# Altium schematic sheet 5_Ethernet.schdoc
size 309 x 223 mm; Symbol: Artery_A4; Device: Artery_A4; Company: Artery Technology; Drawed: SD; Version: 1.3; Page Size: A4; @Project Name: AT-START-A403A V1.3; @Page Count: 5; @Update Date: 2023-11-22; @Create Date: 2022-12-01; @Schematic Name: AT_START_A403A; @Page No: 5; @Page Name: Ethernet
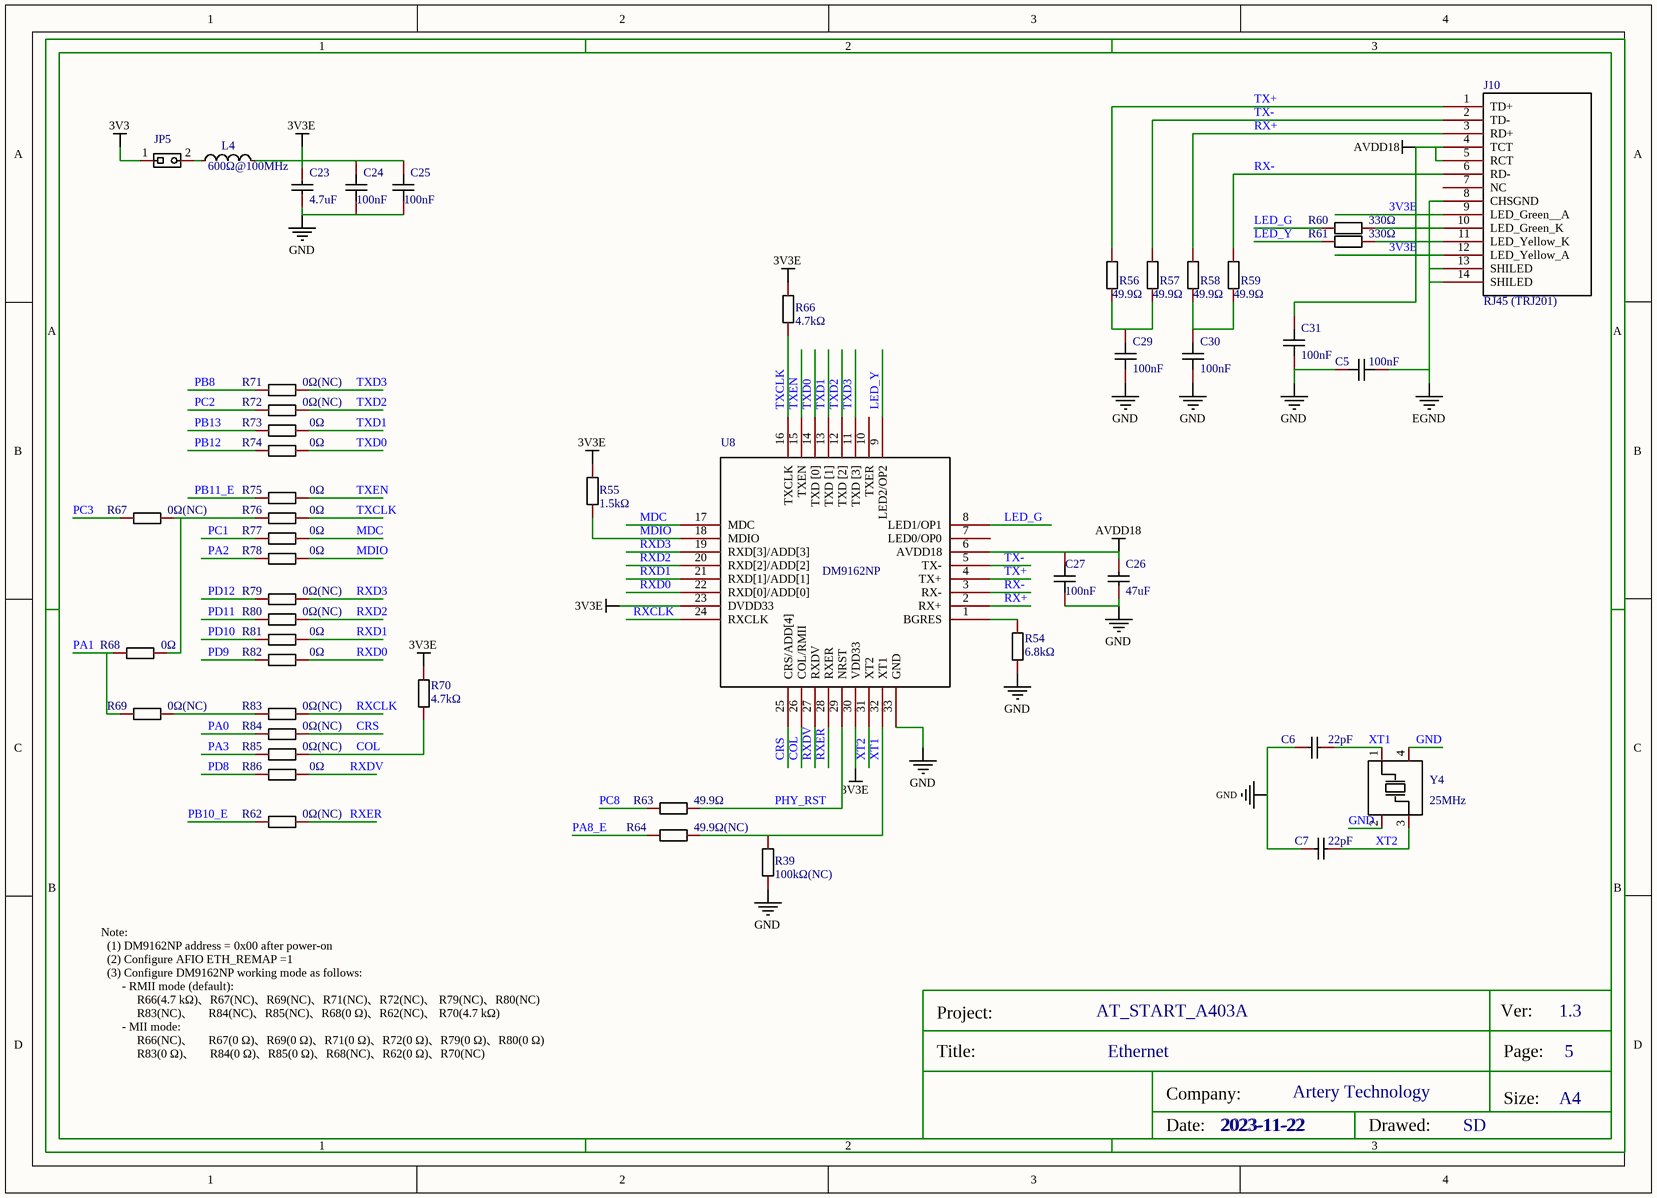
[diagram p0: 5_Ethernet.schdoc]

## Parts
C5  value 100nF  [C0603]  (hidden comment: CC0603KRX7R9BB104)
C6  22pF  [C0603]
C7  22pF  [C0603]
C23  value 4.7uF  [C0603]  (hidden comment: CL10A475KO8NNNC)
C24  value 100nF  [C0603]  (hidden comment: CC0603KRX7R9BB104)
C25  value 100nF  [C0603]  (hidden comment: CC0603KRX7R9BB104)
C26  value 47uF  [C0805]  (hidden comment: CL21A476MQYNNNE)
C27  value 100nF  [C0603]  (hidden comment: CC0603KRX7R9BB104)
C29  value 100nF  [C0603]  (hidden comment: CC0603KRX7R9BB104)
C30  value 100nF  [C0603]  (hidden comment: CC0603KRX7R9BB104)
C31  value 100nF  [C0603]  (hidden comment: CC0603KRX7R9BB104)
J10  RJ45 (TRJ201)  [HR911105A]
JP5  1X2P_2.54M  [HDR1X2]  (value not drawn)
L4  Impedance @ Frequency: 600Ω@100MHz  [L0805]  (hidden comment: GZ2012D601TF)
R39  value 100kΩ(NC)  [R0603]  (hidden comment: 0603WAF1003T5E)
R54  value 6.8kΩ  [R0603]  (hidden comment: 0603WAF6801T5E)
R55  value 1.5kΩ  [R0603]  (hidden comment: 0603WAF1501T5E)
R56  value 49.9Ω  [R0603]  (hidden comment: 0603WAF499JT5E)
R57  value 49.9Ω  [R0603]  (hidden comment: 0603WAF499JT5E)
R58  value 49.9Ω  [R0603]  (hidden comment: 0603WAF499JT5E)
R59  value 49.9Ω  [R0603]  (hidden comment: 0603WAF499JT5E)
R60  value 330Ω  [R0603]  (hidden comment: 0603WAF3300T5E)
R61  value 330Ω  [R0603]  (hidden comment: 0603WAF3300T5E)
R62  value 0Ω(NC)  [R0603]  (hidden comment: 0603WAF0000T5E)
R63  value 49.9Ω  [R0603]  (hidden comment: 0603WAF499JT5E)
R64  value 49.9Ω(NC)  [R0603]  (hidden comment: 0603WAF499JT5E)
R66  value 4.7kΩ  [R0603]  (hidden comment: 0603WAF4701T5E)
R67  value 0Ω(NC)  [R0603]  (hidden comment: 0603WAF0000T5E)
R68  value 0Ω  [R0603]  (hidden comment: 0603WAF0000T5E)
R69  value 0Ω(NC)  [R0603]  (hidden comment: 0603WAF0000T5E)
R70  value 4.7kΩ  [R0603]  (hidden comment: 0603WAF4701T5E)
R71  value 0Ω(NC)  [R0603]  (hidden comment: 0603WAF0000T5E)
R72  value 0Ω(NC)  [R0603]  (hidden comment: 0603WAF0000T5E)
R73  value 0Ω  [R0603]  (hidden comment: 0603WAF0000T5E)
R74  value 0Ω  [R0603]  (hidden comment: 0603WAF0000T5E)
R75  value 0Ω  [R0603]  (hidden comment: 0603WAF0000T5E)
R76  value 0Ω  [R0603]  (hidden comment: 0603WAF0000T5E)
R77  value 0Ω  [R0603]  (hidden comment: 0603WAF0000T5E)
R78  value 0Ω  [R0603]  (hidden comment: 0603WAF0000T5E)
R79  value 0Ω(NC)  [R0603]  (hidden comment: 0603WAF0000T5E)
R80  value 0Ω(NC)  [R0603]  (hidden comment: 0603WAF0000T5E)
R81  value 0Ω  [R0603]  (hidden comment: 0603WAF0000T5E)
R82  value 0Ω  [R0603]  (hidden comment: 0603WAF0000T5E)
R83  value 0Ω(NC)  [R0603]  (hidden comment: 0603WAF0000T5E)
R84  value 0Ω(NC)  [R0603]  (hidden comment: 0603WAF0000T5E)
R85  value 0Ω(NC)  [R0603]  (hidden comment: 0603WAF0000T5E)
R86  value 0Ω  [R0603]  (hidden comment: 0603WAF0000T5E)
U8  DM9162NP  [DM9162NP]
Y4  25MHz  [CRYSTAL-SMD_4P-L5.0-W3.2-BL]

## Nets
3V3: JP5.1
3V3E: C23.2 C24.2 C25.2 J10.9(LED_Green__A) J10.12(LED_Yellow_A) L4.2 R55.1 R66.1 R70.1 U8.23(DVDD33) U8.30(VDD33)
AVDD18: C26.2 C27.2 C31.2 J10.4(TCT) J10.5(RCT) U8.6(AVDD18)
EGND: C5.1 J10.8(CHSGND) J10.13(SHILED) J10.14(SHILED)
GND: C5.2 C6.2 C7.2 C23.1 C24.1 C25.1 C26.1 C27.1 C29.1 C30.1 C31.1 R39.2 R54.1 U8.33(GND) Y4.2(GND) Y4.4(GND)
COL: R70.2 R85.2 U8.26(COL/RMII)
CRS: R84.2 U8.25(CRS/ADD[4])
LED_G: R60.1 U8.8(LED1/OP1)
LED_Y: R61.1 U8.9(LED2/OP2)
MDC: R77.1 U8.17(MDC)
MDIO: R55.2 R78.1 U8.18(MDIO)
PA0: R84.1
PA1: R68.1 R69.2
PA2: R78.2
PA3: R85.1
PA8_E: R64.2
PB8: R71.2
PB10_E: R62.1
PB11_E: R75.2
PB12: R74.2
PB13: R73.2
PC1: R77.2
PC2: R72.2
PC3: R67.2
PC8: R63.2
PD8: R86.1
PD9: R82.1
PD10: R81.1
PD11: R80.2
PD12: R79.2
PHY_RST: R63.1 U8.29(NRST)
RX+: J10.3(RD+) R58.2 U8.2(RX+)
RX-: J10.6(RD-) R59.2 U8.3(RX-)
RXCLK: R83.2 U8.24(RXCLK)
RXD0: R82.2 U8.22(RXD[0]/ADD[0])
RXD1: R81.2 U8.21(RXD[1]/ADD[1])
RXD2: R80.1 U8.20(RXD[2]/ADD[2])
RXD3: R79.1 U8.19(RXD[3]/ADD[3])
RXDV: R86.2 U8.27(RXDV)
RXER: R62.2 U8.28(RXER)
TX+: J10.1(TD+) R56.2 U8.4(TX+)
TX-: J10.2(TD-) R57.2 U8.5(TX-)
TXCLK: R66.2 R76.1 U8.16(TXCLK)
TXD0: R74.1 U8.14(TXD_[0])
TXD1: R73.1 U8.13(TXD_[1])
TXD2: R72.1 U8.12(TXD_[2])
TXD3: R71.1 U8.11(TXD_[3])
TXEN: R75.1 U8.15(TXEN)
XT1: C6.1 R39.1 R64.1 U8.32(XT1) Y4.1(OSC1)
XT2: C7.1 U8.31(XT2) Y4.3(OSC2)
NetC29_2: C29.2 R56.1 R57.1
NetC30_2: C30.2 R58.1 R59.1
NetJ10_10: J10.10(LED_Green_K) R60.2
NetJ10_11: J10.11(LED_Yellow_K) R61.2
NetJP5_2: JP5.2 L4.1
NetR54_2: R54.2 U8.1(BGRES)
NetR67_1: R67.1 R68.2 R76.2
NetR69_1: R69.1 R83.1

Not connected (* = marked no-connect by the designer): J10 7(NC); U8 7(LED0/OP0) 10(TXER)

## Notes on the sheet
- Note:
  (1) DM9162NP address = 0x00 after power-on
  (2) Configure AFIO ETH_REMAP =1
  (3) Configure DM9162NP working mode as follows:
  - RMII mode (default):
  R66(4.7 kΩ)、R67(NC)、R69(NC)、R71(NC)、R72(NC)、 R79(NC)、R80(NC)
  R83(NC)、     R84(NC)、R85(NC)、R68(0 Ω)、R62(NC)、 R70(4.7 kΩ)
  - MII mode:
  R66(NC)、     R67(0 Ω)、R69(0 Ω)、R71(0 Ω)、R72(0 Ω)、R79(0 Ω)、R80(0 Ω)
  R83(0 Ω)、     R84(0 Ω)、R85(0 Ω)、R68(NC)、R62(0 Ω)、R70(NC)
- 2023-11-22

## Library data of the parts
C5 C24 C25 C27 C29-C31 = CC0603KRX7R9BB104: 容值:100nF;精度:±10%;额定电压:50V;材质(温度系数):X7R;; Manufacturer: YAGEO(国巨); Add into BOM: yes; Tolerance: ±10%; Voltage Rated: 50V; Temperature Coefficient: X7R
C6 C7 = 0603CG300J500NT: 容值:30pF;精度:±5%;额定电压:50V;材质(温度系数):C0G;; Manufacturer: FH(风华); Add into BOM: yes; Tolerance: ±5%; Voltage Rated: 50V; Temperature Coefficient: C0G
C23 = CL10A475KO8NNNC: 容值:4.7uF;精度:±10%;额定电压:16V;材质(温度系数):X5R;; Manufacturer: SAMSUNG(三星); Add into BOM: yes; Tolerance: ±10%; Voltage Rated: 16V; Temperature Coefficient: X5R
C26 = CL21A476MQYNNNE: 容值:47uF;精度:±20%;额定电压:6.3V;材质(温度系数):X5R;; Manufacturer: SAMSUNG(三星); Add into BOM: yes; Tolerance: ±20%; Voltage Rated: 6.3V; Temperature Coefficient: X5R
J10 = RJ45 (TRJ201): Symbol: RJ45(HR911105A); Add into BOM: yes; Value: 1
JP5 = 1X2P_2.54M: Symbol: 1X2P,Male,DIP_2.54; Origin Footprint 2: SIP_2P; Add into BOM: yes; Origin Footprint 1: HDR1X2 - SOP
L4 = GZ2012D601TF: 标称阻抗@测试频率:600Ω@100MHz;误差:±25%;直流电阻(RDC):300mΩ;额定电流:500mA;电路数:1;; Manufacturer: Sunlord(顺络); Add into BOM: yes; Tolerance: ±25%; DC Resistance: 300mΩ; Current Rating: 500mA; Circuits: 1; Value: 1
R39 = 0603WAF1003T5E: 电阻类型:厚膜电阻;阻值:100kΩ;精度:±1%;功率:100mW;温度系数:±100ppm/℃;最大工作电压:75V;工作温度范围:-55℃~+155℃;; Manufacturer: UNI-ROYAL(厚声); Add into BOM: yes; Tolerance: ±1%; Power(Watts): 100mW; Overload Voltage (Max): 75V
R54 = 0603WAF6801T5E: 电阻类型:厚膜电阻;阻值:6.8kΩ;精度:±1%;功率:100mW;温度系数:±100ppm/℃;最大工作电压:75V;工作温度范围:-55℃~+155℃;; Manufacturer: UNI-ROYAL(厚声); Add into BOM: yes; Tolerance: ±1%; Power(Watts): 100mW; Overload Voltage (Max): 75V
R55 = 0603WAF1501T5E: 电阻类型:厚膜电阻;阻值:1.5kΩ;精度:±1%;功率:100mW;温度系数:±100ppm/℃;最大工作电压:75V;工作温度范围:-55℃~+155℃;; Manufacturer: UNI-ROYAL(厚声); Add into BOM: yes; Tolerance: ±1%; Power(Watts): 100mW; Overload Voltage (Max): 75V
R56-R59 R63 R64 = 0603WAF499JT5E: 电阻类型:厚膜电阻;阻值:49.9Ω;精度:±1%;功率:100mW;温度系数:±100ppm/℃;最大工作电压:75V;工作温度范围:-55℃~+155℃;; Manufacturer: UNI-ROYAL(厚声); Add into BOM: yes; Tolerance: ±1%; Power(Watts): 100mW; Overload Voltage (Max): 75V
R60 R61 = 0603WAF3300T5E: 电阻类型:厚膜电阻;阻值:330Ω;精度:±1%;功率:100mW;温度系数:±100ppm/℃;最大工作电压:75V;工作温度范围:-55℃~+155℃;; Manufacturer: UNI-ROYAL(厚声); Add into BOM: yes; Tolerance: ±1%; Power(Watts): 100mW; Overload Voltage (Max): 75V
R62 R67-R69 R71-R86 = 0603WAF0000T5E: 电阻类型:厚膜电阻;阻值:0Ω;精度:±1%;功率:100mW;最大工作电压:75V;工作温度范围:-55℃~+155℃;; Manufacturer: UNI-ROYAL(厚声); Add into BOM: yes; Tolerance: ±1%; Power(Watts): 100mW; Overload Voltage (Max): 75V
R66 R70 = 0603WAF4701T5E: 电阻类型:厚膜电阻;阻值:4.7kΩ;精度:±1%;功率:100mW;温度系数:±100ppm/℃;最大工作电压:75V;工作温度范围:-55℃~+155℃;; Manufacturer: UNI-ROYAL(厚声); Add into BOM: yes; Tolerance: ±1%; Power(Watts): 100mW; Overload Voltage (Max): 75V
U8 = DM9162NP: Add into BOM: yes; Value: 1
Y4 = X503225MSB4SI: 晶振类型:贴片无源晶振;频率:25MHz;频率公差:±10ppm;频率稳定度:±50ppm;负载电容:20pF;工作温度:-40℃~+85℃;; Manufacturer: YXC(扬兴晶振); Add into BOM: yes; Crystal Type: 贴片无源晶振; Frequency Tolerance: ±10ppm; Frequency Stability: ±50ppm; Load Capacitance: 20pF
